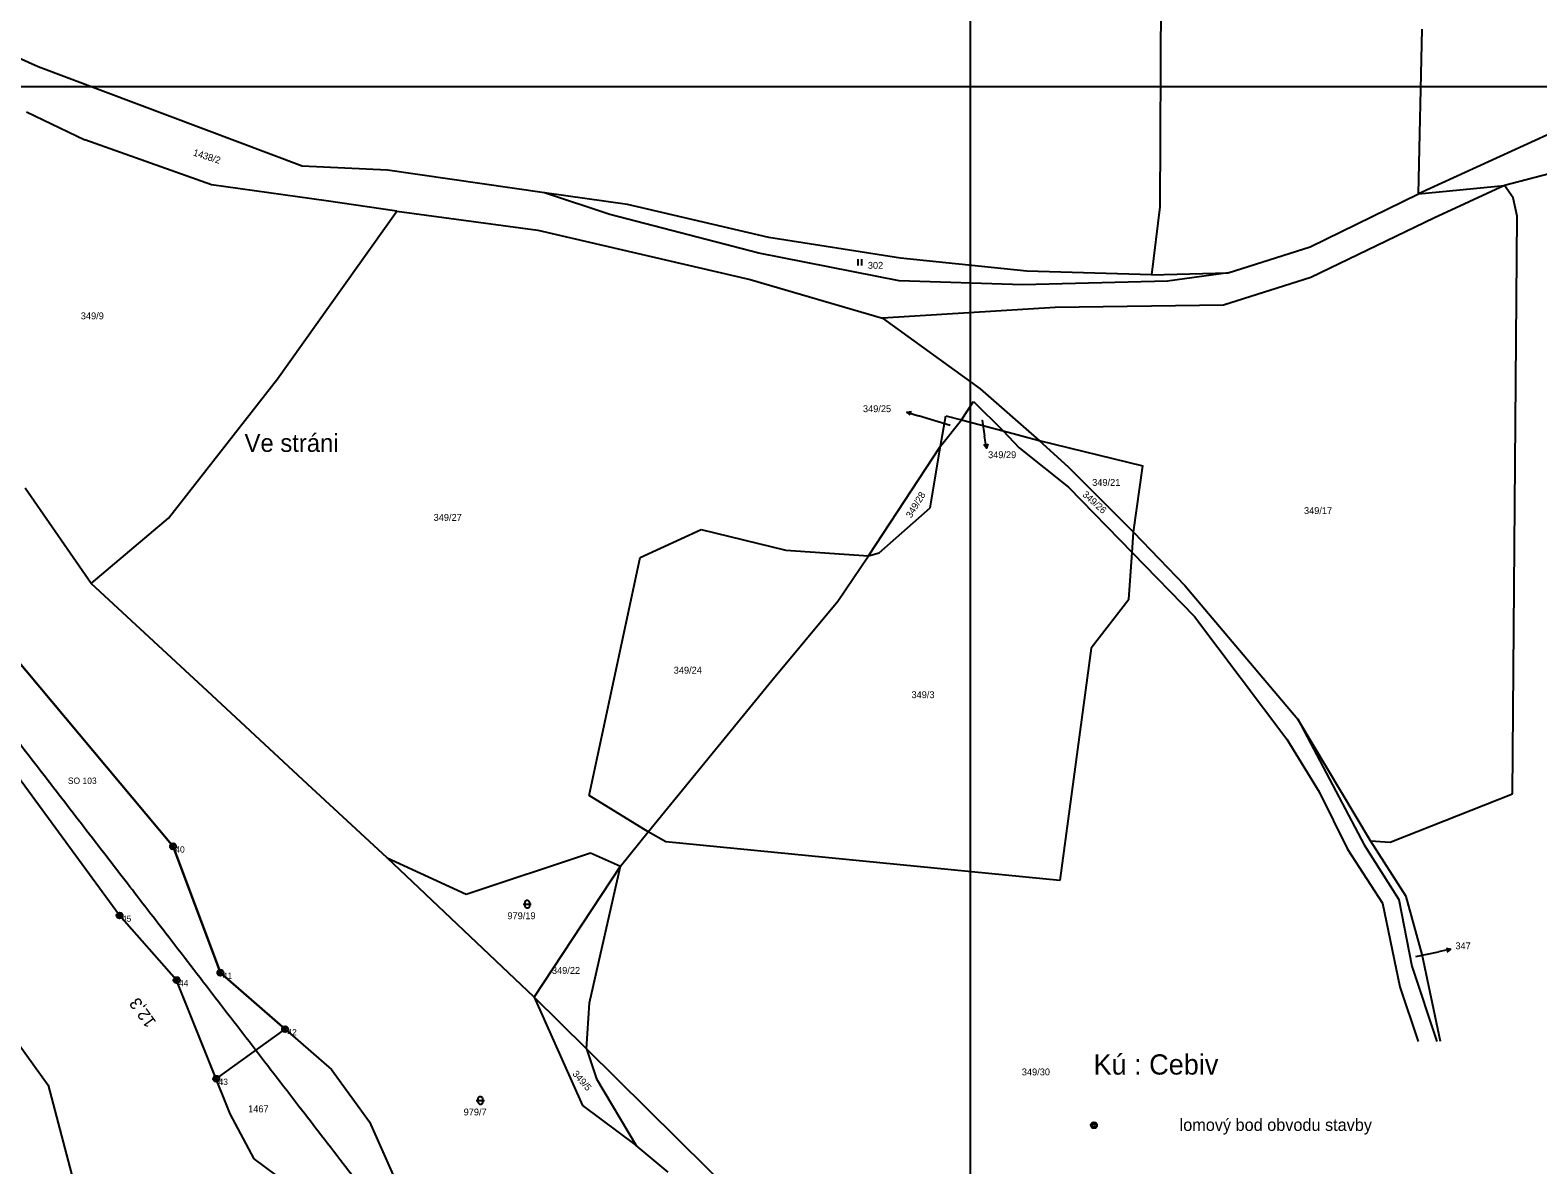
# Model space of a CAD drawing. Extents: x -852001 to -842497, y -1063614 to -1052182.
# Drawn here: x -848982.2 to -848609.9, y -1056471.5 to -1056191.2 of the extents above; entities that cross this region are included whole.
import ezdxf

# ---------------------------------------------------------------- set-up
doc = ezdxf.new("R2010")
doc.units = 0
for name, color, linetype in [('body', 7, 'Continuous'), ('cisla', 7, 'Continuous'), ('Default', 7, 'Continuous'), ('KLADY_ZMVM', 7, 'Continuous'), ('KN_HRANICE', 7, 'Continuous'), ('KN_KULTURY', 7, 'Continuous'), ('KN_PARCELY', 7, 'Continuous'), ('LEGENDA', 7, 'Continuous'), ('obvod_stavby', 7, 'Continuous'), ('so', 7, 'Continuous'), ('Vrstva 7', 7, 'Continuous'), ('Železniční svršek', 7, 'Continuous')]:
    doc.layers.add(name, color=color, linetype=linetype)

# ---------------------------------------------------------------- blocks, each defined once
blk = doc.blocks.new('306')
at = {"layer": 'Default'}
for p, q in [((-0.5, 1.5), (-0.5, 0)), ((0.5, 0), (0.5, 1.5))]:
    blk.add_line(p, q, dxfattribs=at)
blk = doc.blocks.new('316')
at = {"layer": 'Default'}
for points in [[(-1, 1), (0.27, 1), (1, 1)], [(-0.5, 1.5), (-0.4, 1.79), (-0.15, 1.97), (0.16, 1.97), (0.41, 1.79), (0.51, 1.5), (0.51, 0.5), (0.41, 0.21), (0.16, 0.03), (-0.15, 0.03), (-0.4, 0.21), (-0.5, 0.5), (-0.5, 1.5)]]:
    blk.add_lwpolyline(points, dxfattribs=at)
blk = doc.blocks.new('10292')
at = {"layer": 'Default'}
blk.add_line((0, 3), (0, 0), dxfattribs=at)
blk.add_lwpolyline([(-0.5, 2), (0, 3), (0.5, 2)], dxfattribs=at)

msp = doc.modelspace()

# ---------------------------------------------------------------- linework, layer by layer
at = {"layer": 'body'}
for p, q in [((-848946.95, -1056392.82), (-848946.95, -1056392.82)), ((-848960.15, -1056409.91), (-848960.15, -1056409.91)), ((-848935.25, -1056424.04), (-848935.25, -1056424.04)), ((-848946.06, -1056425.85), (-848946.06, -1056425.85)), ((-848919.27, -1056437.97), (-848919.27, -1056437.97)), ((-848936.28, -1056450.21), (-848936.28, -1056450.21))]:
    msp.add_line(p, q, dxfattribs=at)
for centre, radius in [((-848946.95, -1056392.82), 0.75), ((-848946.95, -1056392.82), 0.35), ((-848960.15, -1056409.91), 0.75), ((-848960.15, -1056409.91), 0.35), ((-848935.25, -1056424.04), 0.75), ((-848935.25, -1056424.04), 0.35), ((-848946.06, -1056425.85), 0.75), ((-848946.06, -1056425.85), 0.35), ((-848919.27, -1056437.97), 0.75), ((-848919.27, -1056437.97), 0.35), ((-848936.28, -1056450.21), 0.75), ((-848936.28, -1056450.21), 0.35), ((-848719.52, -1056461.71), 0.75), ((-848719.52, -1056461.71), 0.35)]:
    msp.add_circle(centre, radius, dxfattribs=at)
at = {"layer": 'KLADY_ZMVM'}
msp.add_lwpolyline([(-849375, -1056500), (-848750, -1056500), (-848750, -1056000)], dxfattribs=at)
at = {"layer": 'KN_HRANICE'}
for p, q in [((-848702.93, -1056158.44), (-848703.21, -1056234.89)), ((-848702.93, -1056158.44), (-848703.21, -1056234.89)), ((-848980.22, -1056200.29), (-848999.18, -1056191.91)), ((-848980.22, -1056200.29), (-848999.18, -1056191.91)), ((-848639.31, -1056231.64), (-848638.46, -1056191)), ((-848639.31, -1056231.64), (-848638.46, -1056191)), ((-848915.07, -1056224.84), (-848980.22, -1056200.29)), ((-848915.07, -1056224.84), (-848980.22, -1056200.29)), ((-848983.18, -1056211.44), (-848968.74, -1056218.34)), ((-848983.18, -1056211.44), (-848968.74, -1056218.34)), ((-848604.75, -1056215.87), (-848639.31, -1056231.64)), ((-848604.75, -1056215.87), (-848639.31, -1056231.64)), ((-848937.43, -1056229.47), (-848968.74, -1056218.34)), ((-848937.43, -1056229.47), (-848968.74, -1056218.34)), ((-848577.95, -1056219.08), (-848618.09, -1056229.6)), ((-848577.95, -1056219.08), (-848618.09, -1056229.6)), ((-848893.95, -1056225.83), (-848915.07, -1056224.84)), ((-848893.95, -1056225.83), (-848915.07, -1056224.84)), ((-848855.18, -1056231.4), (-848893.95, -1056225.83)), ((-848855.18, -1056231.4), (-848893.95, -1056225.83)), ((-848909.13, -1056233.4), (-848937.43, -1056229.47)), ((-848909.13, -1056233.4), (-848937.43, -1056229.47)), ((-848639.31, -1056231.64), (-848618.09, -1056229.6)), ((-848639.31, -1056231.64), (-848618.09, -1056229.6)), ((-848618.09, -1056229.6), (-848635.58, -1056237.7)), ((-848618.09, -1056229.6), (-848635.58, -1056237.7)), ((-848615.96, -1056232.64), (-848618.09, -1056229.6)), ((-848615.96, -1056232.64), (-848618.09, -1056229.6)), ((-848891.67, -1056235.93), (-848909.13, -1056233.4)), ((-848891.67, -1056235.93), (-848909.13, -1056233.4)), ((-848834.73, -1056234.34), (-848855.18, -1056231.4)), ((-848839.05, -1056236.78), (-848855.18, -1056231.4)), ((-848834.73, -1056234.34), (-848855.18, -1056231.4)), ((-848839.05, -1056236.78), (-848855.18, -1056231.4)), ((-848799.76, -1056242.49), (-848834.73, -1056234.34)), ((-848799.76, -1056242.49), (-848834.73, -1056234.34)), ((-848703.21, -1056234.89), (-848705.29, -1056251.7)), ((-848703.21, -1056234.89), (-848705.29, -1056251.7)), ((-848666.08, -1056244.77), (-848639.31, -1056231.64)), ((-848666.08, -1056244.77), (-848639.31, -1056231.64)), ((-848614.99, -1056237.17), (-848615.96, -1056232.64)), ((-848614.99, -1056237.17), (-848615.96, -1056232.64)), ((-848921.16, -1056277.37), (-848891.67, -1056235.93)), ((-848921.16, -1056277.37), (-848891.67, -1056235.93)), ((-848891.67, -1056235.93), (-848856.82, -1056240.61)), ((-848891.67, -1056235.93), (-848856.82, -1056240.61)), ((-848802.24, -1056246.31), (-848839.05, -1056236.78)), ((-848802.24, -1056246.31), (-848839.05, -1056236.78)), ((-848635.58, -1056237.7), (-848665.92, -1056252.36)), ((-848635.58, -1056237.7), (-848665.92, -1056252.36)), ((-848616.11, -1056379.89), (-848614.99, -1056237.17)), ((-848616.11, -1056379.89), (-848614.99, -1056237.17)), ((-848856.82, -1056240.61), (-848804.39, -1056252.86)), ((-848856.82, -1056240.61), (-848804.39, -1056252.86)), ((-848767.32, -1056247.53), (-848799.76, -1056242.49)), ((-848767.32, -1056247.53), (-848799.76, -1056242.49)), ((-848686.34, -1056251.17), (-848666.08, -1056244.77)), ((-848686.34, -1056251.17), (-848666.08, -1056244.77)), ((-848767.63, -1056253.16), (-848802.24, -1056246.31)), ((-848767.63, -1056253.16), (-848802.24, -1056246.31)), ((-848736.12, -1056250.74), (-848767.32, -1056247.53)), ((-848736.12, -1056250.74), (-848767.32, -1056247.53)), ((-848804.39, -1056252.86), (-848771.71, -1056262.35)), ((-848804.39, -1056252.86), (-848771.71, -1056262.35)), ((-848737.06, -1056254.14), (-848767.63, -1056253.16)), ((-848737.06, -1056254.14), (-848767.63, -1056253.16)), ((-848701.32, -1056253.27), (-848737.06, -1056254.14)), ((-848701.32, -1056253.27), (-848737.06, -1056254.14)), ((-848705.29, -1056251.7), (-848736.12, -1056250.74)), ((-848705.29, -1056251.7), (-848736.12, -1056250.74)), ((-848705.29, -1056251.7), (-848686.34, -1056251.17)), ((-848705.29, -1056251.7), (-848686.34, -1056251.17)), ((-848686.34, -1056251.17), (-848701.32, -1056253.27)), ((-848686.34, -1056251.17), (-848701.32, -1056253.27)), ((-848665.92, -1056252.36), (-848687.54, -1056259.16)), ((-848665.92, -1056252.36), (-848687.54, -1056259.16)), ((-848729.07, -1056259.72), (-848771.71, -1056262.35)), ((-848729.07, -1056259.72), (-848771.71, -1056262.35)), ((-848687.54, -1056259.16), (-848729.07, -1056259.72)), ((-848687.54, -1056259.16), (-848729.07, -1056259.72)), ((-848771.71, -1056262.35), (-848747.58, -1056279.8)), ((-848771.71, -1056262.35), (-848747.58, -1056279.8)), ((-848948.08, -1056311.8), (-848921.16, -1056277.37)), ((-848948.08, -1056311.8), (-848921.16, -1056277.37)), ((-848752.25, -1056287.49), (-848749.25, -1056282.93)), ((-848752.25, -1056287.49), (-848749.25, -1056282.93)), ((-848749.25, -1056282.93), (-848741.94, -1056290.17)), ((-848749.25, -1056282.93), (-848741.94, -1056290.17)), ((-848747.58, -1056279.8), (-848733.01, -1056292.62)), ((-848747.58, -1056279.8), (-848733.01, -1056292.62)), ((-848757.38, -1056293.96), (-848756.1, -1056286.49)), ((-848757.38, -1056293.96), (-848756.1, -1056286.49)), ((-848756.1, -1056286.49), (-848752.25, -1056287.49)), ((-848756.1, -1056286.49), (-848752.25, -1056287.49)), ((-848757.38, -1056293.96), (-848752.25, -1056287.49)), ((-848757.38, -1056293.96), (-848752.25, -1056287.49)), ((-848752.25, -1056287.49), (-848741.94, -1056290.17)), ((-848752.25, -1056287.49), (-848741.94, -1056290.17)), ((-848741.94, -1056290.17), (-848738.01, -1056294.38)), ((-848741.94, -1056290.17), (-848733.01, -1056292.62)), ((-848741.94, -1056290.17), (-848738.01, -1056294.38)), ((-848741.94, -1056290.17), (-848733.01, -1056292.62)), ((-848775.15, -1056321.05), (-848757.38, -1056293.96)), ((-848775.15, -1056321.05), (-848757.38, -1056293.96)), ((-848759.99, -1056309.21), (-848757.38, -1056293.96)), ((-848759.99, -1056309.21), (-848757.38, -1056293.96)), ((-848738.01, -1056294.38), (-848725.77, -1056304.15)), ((-848738.01, -1056294.38), (-848725.77, -1056304.15)), ((-848733.01, -1056292.62), (-848707.39, -1056298.87)), ((-848733.01, -1056292.62), (-848725.85, -1056299.06)), ((-848733.01, -1056292.62), (-848707.39, -1056298.87)), ((-848733.01, -1056292.62), (-848725.85, -1056299.06)), ((-848725.85, -1056299.06), (-848709.7, -1056315.2)), ((-848725.85, -1056299.06), (-848709.7, -1056315.2)), ((-848709.7, -1056315.2), (-848707.39, -1056298.87)), ((-848709.7, -1056315.2), (-848707.39, -1056298.87)), ((-848967.17, -1056327.9), (-848983.5, -1056304.39)), ((-848967.17, -1056327.9), (-848983.5, -1056304.39)), ((-848725.77, -1056304.15), (-848710.05, -1056320.23)), ((-848725.77, -1056304.15), (-848710.05, -1056320.23)), ((-848772.56, -1056320.34), (-848759.99, -1056309.21)), ((-848772.56, -1056320.34), (-848759.99, -1056309.21)), ((-848967.17, -1056327.9), (-848948.08, -1056311.8)), ((-848967.17, -1056327.9), (-848948.08, -1056311.8)), ((-848831.56, -1056321.52), (-848816.55, -1056314.6)), ((-848831.56, -1056321.52), (-848816.55, -1056314.6)), ((-848816.55, -1056314.6), (-848795.6, -1056319.68)), ((-848816.55, -1056314.6), (-848795.6, -1056319.68)), ((-848710.05, -1056320.23), (-848709.7, -1056315.2)), ((-848710.05, -1056320.23), (-848709.7, -1056315.2)), ((-848709.7, -1056315.2), (-848697.02, -1056328.41)), ((-848709.7, -1056315.2), (-848697.02, -1056328.41)), ((-848795.6, -1056319.68), (-848775.15, -1056321.05)), ((-848795.6, -1056319.68), (-848775.15, -1056321.05)), ((-848775.15, -1056321.05), (-848772.56, -1056320.34)), ((-848775.15, -1056321.05), (-848772.56, -1056320.34)), ((-848710.86, -1056331.85), (-848710.05, -1056320.23)), ((-848710.86, -1056331.85), (-848710.05, -1056320.23)), ((-848710.05, -1056320.23), (-848694.67, -1056336.06)), ((-848710.05, -1056320.23), (-848694.67, -1056336.06)), ((-848844.14, -1056380.26), (-848831.56, -1056321.52)), ((-848844.14, -1056380.26), (-848831.56, -1056321.52)), ((-848782.79, -1056332.3), (-848775.15, -1056321.05)), ((-848782.79, -1056332.3), (-848775.15, -1056321.05)), ((-848938.42, -1056354.46), (-848967.17, -1056327.9)), ((-848938.42, -1056354.46), (-848967.17, -1056327.9)), ((-848697.02, -1056328.41), (-848669.13, -1056361.38)), ((-848697.02, -1056328.41), (-848669.13, -1056361.38)), ((-848799.02, -1056351.87), (-848782.79, -1056332.3)), ((-848799.02, -1056351.87), (-848782.79, -1056332.3)), ((-848710.86, -1056331.85), (-848720.19, -1056343.89)), ((-848710.86, -1056331.85), (-848720.19, -1056343.89)), ((-848694.67, -1056336.06), (-848671.9, -1056366.37)), ((-848694.67, -1056336.06), (-848671.9, -1056366.37)), ((-848990.06, -1056341.42), (-848946.95, -1056392.82)), ((-848990.06, -1056341.42), (-848946.95, -1056392.82)), ((-848720.19, -1056343.89), (-848727.89, -1056401.29)), ((-848720.19, -1056343.89), (-848727.89, -1056401.29)), ((-848829.61, -1056389.21), (-848799.02, -1056351.87)), ((-848829.61, -1056389.21), (-848799.02, -1056351.87)), ((-848913.71, -1056377.5), (-848938.42, -1056354.46)), ((-848913.71, -1056377.5), (-848938.42, -1056354.46)), ((-848669.13, -1056361.38), (-848652.75, -1056392.45)), ((-848651.22, -1056391.42), (-848669.13, -1056361.38)), ((-848669.13, -1056361.38), (-848652.75, -1056392.45)), ((-848651.22, -1056391.42), (-848669.13, -1056361.38)), ((-848671.9, -1056366.37), (-848663.87, -1056379.33)), ((-848671.9, -1056366.37), (-848663.87, -1056379.33)), ((-848960.15, -1056409.91), (-848986.01, -1056374.55)), ((-848960.15, -1056409.91), (-848986.01, -1056374.55)), ((-848894.05, -1056395.69), (-848913.71, -1056377.5)), ((-848894.05, -1056395.69), (-848913.71, -1056377.5)), ((-848663.87, -1056379.33), (-848656.86, -1056393.51)), ((-848663.87, -1056379.33), (-848656.86, -1056393.51)), ((-848646.38, -1056391.76), (-848616.11, -1056379.89)), ((-848646.38, -1056391.76), (-848616.11, -1056379.89)), ((-848829.61, -1056389.21), (-848844.14, -1056380.26)), ((-848829.61, -1056389.21), (-848844.14, -1056380.26)), ((-848836.41, -1056397.73), (-848829.61, -1056389.21)), ((-848836.41, -1056397.73), (-848829.61, -1056389.21)), ((-848825.23, -1056391.74), (-848829.61, -1056389.21)), ((-848825.23, -1056391.74), (-848829.61, -1056389.21)), ((-848946.95, -1056392.82), (-848935.25, -1056424.04)), ((-848946.95, -1056392.82), (-848935.25, -1056424.04)), ((-848874.53, -1056404.65), (-848843.82, -1056394.4)), ((-848874.53, -1056404.65), (-848843.82, -1056394.4)), ((-848843.82, -1056394.4), (-848836.41, -1056397.73)), ((-848843.82, -1056394.4), (-848836.41, -1056397.73)), ((-848727.89, -1056401.29), (-848825.23, -1056391.74)), ((-848727.89, -1056401.29), (-848825.23, -1056391.74)), ((-848656.86, -1056393.51), (-848648.2, -1056406.88)), ((-848656.86, -1056393.51), (-848648.2, -1056406.88)), ((-848652.75, -1056392.45), (-848644.19, -1056405.99)), ((-848652.75, -1056392.45), (-848644.19, -1056405.99)), ((-848651.22, -1056391.42), (-848646.38, -1056391.76)), ((-848642.4, -1056405.19), (-848651.22, -1056391.42)), ((-848651.22, -1056391.42), (-848646.38, -1056391.76)), ((-848642.4, -1056405.19), (-848651.22, -1056391.42)), ((-848857.75, -1056430.11), (-848894.05, -1056395.69)), ((-848894.05, -1056395.69), (-848874.53, -1056404.65)), ((-848857.75, -1056430.11), (-848894.05, -1056395.69)), ((-848894.05, -1056395.69), (-848874.53, -1056404.65)), ((-848857.75, -1056430.11), (-848836.41, -1056397.73)), ((-848857.75, -1056430.11), (-848836.41, -1056397.73)), ((-848844.06, -1056431.47), (-848836.41, -1056397.73)), ((-848844.06, -1056431.47), (-848836.41, -1056397.73)), ((-848644.19, -1056405.99), (-848641.03, -1056422.42)), ((-848644.19, -1056405.99), (-848641.03, -1056422.42)), ((-848638.4, -1056419.53), (-848642.4, -1056405.19)), ((-848638.4, -1056419.53), (-848642.4, -1056405.19)), ((-848946.06, -1056425.85), (-848960.15, -1056409.91)), ((-848946.06, -1056425.85), (-848960.15, -1056409.91)), ((-848648.2, -1056406.88), (-848643.95, -1056427.54)), ((-848648.2, -1056406.88), (-848643.95, -1056427.54)), ((-849001.93, -1056418.36), (-848977.76, -1056451.81)), ((-849001.93, -1056418.36), (-848977.76, -1056451.81)), ((-848633.93, -1056441.01), (-848638.4, -1056419.53)), ((-848633.93, -1056441.01), (-848638.4, -1056419.53)), ((-848935.25, -1056424.04), (-848907.81, -1056447.97)), ((-848935.25, -1056424.04), (-848907.81, -1056447.97)), ((-848641.03, -1056422.42), (-848634.85, -1056441.01)), ((-848641.03, -1056422.42), (-848634.85, -1056441.01)), ((-848932.8, -1056458.88), (-848946.06, -1056425.85)), ((-848932.8, -1056458.88), (-848946.06, -1056425.85)), ((-848643.95, -1056427.54), (-848639.41, -1056441.01)), ((-848643.95, -1056427.54), (-848639.41, -1056441.01)), ((-848844.87, -1056442.82), (-848857.75, -1056430.11)), ((-848857.75, -1056430.11), (-848845.82, -1056456.79)), ((-848844.87, -1056442.82), (-848857.75, -1056430.11)), ((-848857.75, -1056430.11), (-848845.82, -1056456.79)), ((-848844.87, -1056442.82), (-848844.06, -1056431.47)), ((-848844.87, -1056442.82), (-848844.06, -1056431.47)), ((-848788.89, -1056498.09), (-848844.87, -1056442.82)), ((-848844.87, -1056442.82), (-848842.4, -1056450.27)), ((-848788.89, -1056498.09), (-848844.87, -1056442.82)), ((-848844.87, -1056442.82), (-848842.4, -1056450.27)), ((-848907.81, -1056447.97), (-848898.41, -1056460.89)), ((-848907.81, -1056447.97), (-848898.41, -1056460.89)), ((-848842.4, -1056450.27), (-848832.57, -1056466.67)), ((-848842.4, -1056450.27), (-848832.57, -1056466.67)), ((-848977.76, -1056451.81), (-848967.94, -1056489.14)), ((-848977.76, -1056451.81), (-848967.94, -1056489.14)), ((-848845.82, -1056456.79), (-848832.57, -1056466.67)), ((-848845.82, -1056456.79), (-848832.57, -1056466.67)), ((-848926.93, -1056469.99), (-848932.8, -1056458.88)), ((-848926.93, -1056469.99), (-848932.8, -1056458.88)), ((-848898.41, -1056460.89), (-848886.21, -1056488.24)), ((-848898.41, -1056460.89), (-848886.21, -1056488.24)), ((-848824.7, -1056473.29), (-848832.57, -1056466.67)), ((-848824.7, -1056473.29), (-848832.57, -1056466.67)), ((-848892.25, -1056495.68), (-848926.93, -1056469.99)), ((-848892.25, -1056495.68), (-848926.93, -1056469.99))]:
    msp.add_line(p, q, dxfattribs=at)
at = {"layer": 'KN_PARCELY'}
for p, q in [((-848755, -1056288.92), (-848762.82, -1056286.48)), ((-848755, -1056288.92), (-848762.82, -1056286.48)), ((-848747.13, -1056287.53), (-848746.53, -1056291.5)), ((-848747.13, -1056287.53), (-848746.53, -1056291.5)), ((-848640.02, -1056420.06), (-848634.4, -1056418.87)), ((-848640.02, -1056420.06), (-848634.4, -1056418.87))]:
    msp.add_line(p, q, dxfattribs=at)
at = {"layer": 'LEGENDA'}
msp.add_lwpolyline([(-849142.95, -1056625.24), (-848548.95, -1056625.24), (-848548.95, -1056205.24), (-849142.95, -1056205.24)], close=True, dxfattribs=at)
at = {"layer": 'obvod_stavby'}
msp.add_line((-848936.28, -1056450.22), (-848919.27, -1056437.97), dxfattribs=at)
for points in [[(-848936.28, -1056450.22), (-848946.06, -1056425.85), (-848960.15, -1056409.91), (-848986.01, -1056374.55), (-849002.37, -1056352.82), (-848990.06, -1056341.42)], [(-848919.27, -1056437.97), (-848935.25, -1056424.04), (-848946.95, -1056392.82), (-848990.06, -1056341.42)]]:
    msp.add_lwpolyline(points, dxfattribs=at)
at = {"layer": 'Železniční svršek'}
msp.add_open_spline([(-848892.81, -1056486.91), (-848898.96, -1056478.95), (-848904.39, -1056471.91), (-848910.36, -1056464.18), (-848915.68, -1056457.29), (-848922.02, -1056449.05), (-848928.2, -1056441.01), (-848934.22, -1056433.18), (-848940.17, -1056425.45), (-848946.67, -1056417), (-848952.25, -1056409.77), (-848955.57, -1056405.45), (-848960.77, -1056398.71), (-848966.2, -1056391.67), (-848971.61, -1056384.64), (-848977.18, -1056377.42), (-848982.34, -1056370.71), (-848987.69, -1056363.77), (-848993.84, -1056355.79), (-848999.77, -1056348.09), (-849005.4, -1056340.62), (-849010.95, -1056332.79), (-849016.27, -1056324.7), (-849020.78, -1056317.03), (-849025.01, -1056309.08), (-849028.91, -1056301.1), (-849032.78, -1056292.63), (-849036.57, -1056284.16)], degree=3, dxfattribs=at)

# ---------------------------------------------------------------- block references
at = {"layer": 'KN_KULTURY'}
for name, p in [('306', (-848777.31, -1056249.33)), ('306', (-848777.31, -1056249.33)), ('316', (-848859.46, -1056408.12)), ('316', (-848859.46, -1056408.12)), ('316', (-848871.05, -1056456.58)), ('316', (-848871.05, -1056456.58))]:
    msp.add_blockref(name, p, dxfattribs=at)
at = {"layer": 'KN_PARCELY'}
for p, rotation in [((-848762.82, -1056286.48), 72.708344), ((-848762.82, -1056286.48), 72.708344), ((-848746.53, -1056291.5), -171.38229400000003), ((-848746.53, -1056291.5), -171.38229400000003), ((-848634.4, -1056418.87), -78.04746899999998), ((-848634.4, -1056418.87), -78.04746899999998)]:
    msp.add_blockref('10292', p, dxfattribs=dict(at, rotation=rotation))

# ---------------------------------------------------------------- texts
at = {"layer": 'cisla'}
for s, p in [(' 40', (-848946.95, -1056394.37)), (' 45', (-848960.15, -1056411.46)), (' 41', (-848935.25, -1056425.59)), (' 44', (-848946.06, -1056427.4)), (' 42', (-848919.27, -1056439.52)), (' 43', (-848936.28, -1056451.76))]:
    msp.add_text(s, height=1.552, dxfattribs=at).set_placement(p)
at = {"layer": 'KN_PARCELY'}
for s, rotation, p in [('1438/2', 342.342, (-848942.14, -1056222.18)), ('1438/2', 342.342, (-848942.14, -1056222.18)), ('349/28', 58.556, (-848764.63, -1056311.88)), ('349/28', 58.556, (-848764.63, -1056311.88)), ('349/26', 317.992, (-848722.5, -1056306.15)), ('349/26', 317.992, (-848722.5, -1056306.15)), ('349/5', 311.001, (-848848.43, -1056449.1)), ('349/5', 311.001, (-848848.43, -1056449.1))]:
    msp.add_text(s, height=1.7, rotation=rotation, dxfattribs=at).set_placement(p)
for s, height, p in [('302', 1.7, (-848775.35, -1056250.18)), ('302', 1.7, (-848775.35, -1056250.18)), ('349/9', 1.7, (-848969.73, -1056262.66)), ('349/9', 1.7, (-848969.73, -1056262.66)), ('349/25', 1.7, (-848776.55, -1056285.59)), ('349/25', 1.7, (-848776.55, -1056285.59)), ('Ve stráni', 4.4, (-848929.28, -1056295.4)), ('Ve stráni', 4.4, (-848929.28, -1056295.4)), ('349/25', 0.1, (-848755.29, -1056288.92)), ('349/25', 0.1, (-848755.29, -1056288.92)), ('349/29', 0.1, (-848747.42, -1056287.53)), ('349/29', 0.1, (-848747.42, -1056287.53)), ('349/29', 1.7, (-848745.65, -1056296.95)), ('349/29', 1.7, (-848745.65, -1056296.95)), ('349/21', 1.7, (-848719.94, -1056303.79)), ('349/21', 1.7, (-848719.94, -1056303.79)), ('349/17', 1.7, (-848667.63, -1056310.76)), ('349/17', 1.7, (-848667.63, -1056310.76)), ('349/27', 1.7, (-848882.59, -1056312.44)), ('349/27', 1.7, (-848882.59, -1056312.44)), ('349/24', 1.7, (-848823.29, -1056350.17)), ('349/24', 1.7, (-848823.29, -1056350.17)), ('349/3', 1.7, (-848764.57, -1056356.22)), ('349/3', 1.7, (-848764.57, -1056356.22)), ('979/19', 1.7, (-848864.36, -1056410.82)), ('979/19', 1.7, (-848864.36, -1056410.82)), ('347', 1.7, (-848630.23, -1056418.25)), ('347', 1.7, (-848630.23, -1056418.25)), ('347', 0.1, (-848640.16, -1056420.06)), ('347', 0.1, (-848640.16, -1056420.06)), ('349/22', 1.7, (-848853.37, -1056424.32)), ('349/22', 1.7, (-848853.37, -1056424.32)), ('349/30', 1.7, (-848737.32, -1056449.39)), ('349/30', 1.7, (-848737.32, -1056449.39)), ('1467', 1.7, (-848928.4, -1056458.5)), ('979/7', 1.7, (-848875.18, -1056459.28)), ('979/7', 1.7, (-848875.18, -1056459.28))]:
    msp.add_text(s, height=height, dxfattribs=at).set_placement(p)
at = {"layer": 'LEGENDA'}
for s, height, p in [('Kú : Cebiv', 5, (-848719.62, -1056449.19)), ('lomový bod obvodu stavby', 3, (-848698.34, -1056463.1))]:
    msp.add_text(s, height=height, dxfattribs=at).set_placement(p)
at = {"layer": 'so'}
msp.add_text('SO 103', height=1.567, rotation=360, dxfattribs=at).set_placement((-848972.92, -1056377.4))
at = {"layer": 'Vrstva 7'}
msp.add_text('12,3', height=3, rotation=125.7923, dxfattribs=at).set_placement((-848950.98, -1056436.23))

doc.saveas('drawing.dxf')
